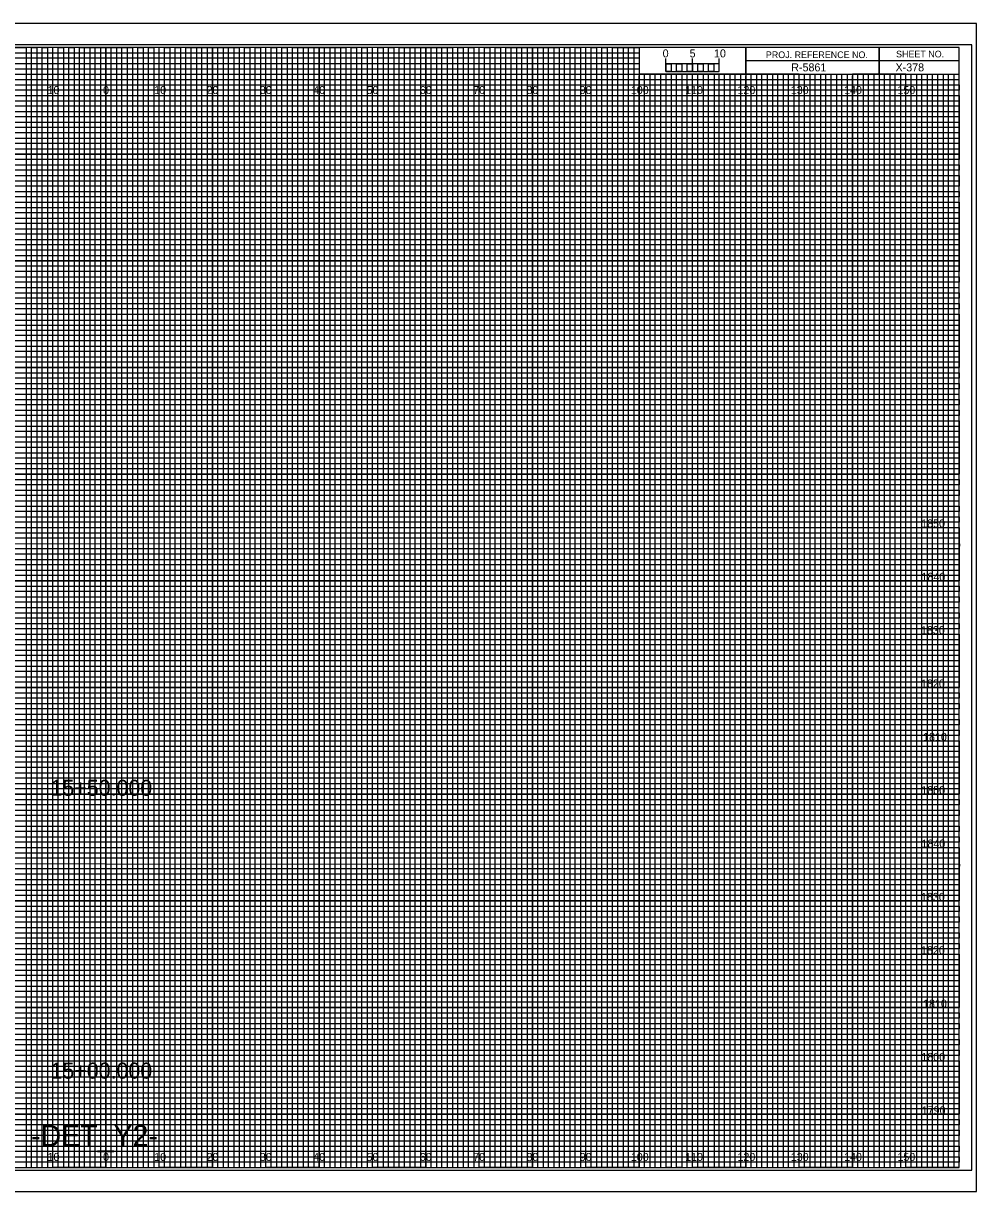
# Model space of a CAD drawing. Extents: x -13 to 323, y -5 to 874.
# Drawn here: x 144.5 to 323.3, y 655.5 to 874.5 of the extents above; entities that cross this region are included whole.
import ezdxf

# ---------------------------------------------------------------- set-up
doc = ezdxf.new("R2010")
doc.units = 0
for name, color, linetype in [('Prop Horizontal Alignment', 7, 'Continuous'), ('Prop XS Alignment Label', 7, 'Continuous'), ('Prop XS Bar Scale Labels', 7, 'Continuous'), ('Prop XS Earthwork Shape', 7, 'Continuous'), ('Prop XS Project Number', 7, 'Continuous'), ('Prop XS Sheet Number', 7, 'Continuous'), ('Raster_Level_0', 7, 'Continuous'), ('Scratch_Level_3', 7, 'Continuous'), ('Sheet Cross Section CELL', 7, 'Continuous'), ('Sheet Cross Section Grid Middle CELL', 7, 'Continuous'), ('Sheet Cross Section Grid Minor 1 CELL', 7, 'Continuous'), ('Sheet Cross Section Grid Minor 2 CELL', 7, 'Continuous'), ('Sheet Cross Section Scale CELL', 7, 'Continuous'), ('Sheet Cutting Line CELL', 7, 'Continuous'), ('Sheet DOT Grid CELL', 7, 'Continuous'), ('Sheet Plot Border Inside CELL', 7, 'Continuous'), ('Sheet Plot Border Outside CELL', 7, 'Continuous')]:
    doc.layers.add(name, color=color, linetype=linetype)

msp = doc.modelspace()

# ---------------------------------------------------------------- linework, layer by layer
at = {"layer": 'Prop XS Earthwork Shape'}
for p, q in [((150, 870), (140, 870)), ((150, 660), (150, 870)), ((170, 870), (160, 870)), ((160, 870), (160, 660)), ((170, 660), (170, 870)), ((190, 870), (180, 870)), ((180, 870), (180, 660)), ((190, 660), (190, 870)), ((210, 870), (200, 870)), ((200, 870), (200, 660)), ((210, 660), (210, 870)), ((230, 870), (220, 870)), ((220, 870), (220, 660)), ((230, 660), (230, 870)), ((250, 870), (240, 870)), ((240, 870), (240, 660)), ((250, 660), (250, 870)), ((260, 870), (260, 660)), ((270, 660), (270, 865)), ((290, 865), (280, 865)), ((280, 865), (280, 660)), ((290, 660), (290, 865)), ((310, 865), (300, 865)), ((300, 865), (300, 660)), ((310, 660), (310, 865)), ((160, 660), (150, 660)), ((180, 660), (170, 660)), ((200, 660), (190, 660)), ((220, 660), (210, 660)), ((240, 660), (230, 660)), ((260, 660), (250, 660)), ((280, 660), (270, 660)), ((300, 660), (290, 660)), ((320, 660), (310, 660)), ((320, 660), (320, 660))]:
    msp.add_line(p, q, dxfattribs=at)
for points in [[(0, 860), (320, 860), (320, 850), (0, 850)], [(0, 840), (320, 840), (320, 830), (0, 830)], [(0, 820), (320, 820), (320, 810), (0, 810)], [(0, 800), (320, 800), (320, 790), (0, 790)], [(0, 780), (320, 780), (320, 770), (0, 770)], [(0, 760), (320, 760), (320, 750), (0, 750)], [(0, 740), (320, 740), (320, 730), (0, 730)], [(0, 720), (320, 720), (320, 710), (0, 710)], [(0, 700), (320, 700), (320, 690), (0, 690)], [(0, 680), (320, 680), (320, 670), (0, 670)]]:
    msp.add_lwpolyline(points, dxfattribs=at)
at = {"layer": 'Sheet Cross Section CELL'}
for p, q in [((305, 870), (305, 865)), ((305, 865), (305, 870)), ((280, 867.5), (280, 865)), ((320, 867.49), (280, 867.49)), ((280, 865), (320, 865))]:
    msp.add_line(p, q, dxfattribs=at)
for points in [[(320, 870), (0, 870), (0, 660), (320, 660)], [(280, 870), (260, 870), (260, 865.03), (280, 865.03)], [(320, 870), (280, 870), (280, 865), (320, 865)]]:
    msp.add_lwpolyline(points, close=True, dxfattribs=at)
at = {"layer": 'Sheet Cross Section Grid Middle CELL'}
for points in [[(135, 870), (145, 870), (145, 660), (155, 660), (155, 870), (165, 870), (165, 660), (175, 660), (175, 870), (185, 870), (185, 660), (195, 660), (195, 870), (205, 870), (205, 660), (215, 660), (215, 870), (225, 870), (225, 660), (235, 660), (235, 870), (245, 870), (245, 660), (255, 660), (255, 870), (259.93, 870), (260, 870), (260, 865), (264.99, 865), (264.99, 660), (275, 660), (275, 865), (285, 865), (285, 660), (295, 660), (295, 865), (305, 865), (305, 660), (315, 660), (315, 865)], [(0, 865), (275, 865)], [(0, 845), (320, 845), (320, 855), (0, 855)], [(0, 825), (320, 825), (320, 835), (0, 835)], [(0, 805), (320, 805), (320, 815), (0, 815)], [(0, 785), (320, 785), (320, 795), (0, 795)], [(0, 765), (320, 765), (320, 775), (0, 775)], [(0, 745), (320, 745), (320, 755), (0, 755)], [(0, 725), (320, 725), (320, 735), (0, 735)], [(0, 705), (320, 705), (320, 715), (0, 715)], [(0, 685), (320, 685), (320, 695), (0, 695)], [(0, 665), (320, 665), (320, 675), (0, 675)]]:
    msp.add_lwpolyline(points, dxfattribs=at)
at = {"layer": 'Sheet Cross Section Grid Minor 1 CELL'}
for p, q in [((0, 869), (260, 869)), ((260, 867.98), (0, 867.98)), ((260, 869), (260, 867.98)), ((0, 867), (260, 867)), ((260, 865.89), (0, 865.89)), ((260, 867), (260, 865.89)), ((0, 864), (320, 864))]:
    msp.add_line(p, q, dxfattribs=at)
for points in [[(0, 863), (270, 863), (320, 863), (320, 862), (0, 862)], [(0, 861), (320, 861), (320, 859), (0, 859)], [(0, 858), (320, 858), (320, 857), (0, 856.98)], [(0, 856), (320, 856), (320, 854), (0, 854)], [(0, 853), (320, 853), (320, 852), (0, 852)], [(0, 851), (320, 851), (320, 849), (0, 849)], [(0, 848), (320, 848), (320, 847), (0, 847)], [(0, 846), (320, 846), (320, 844), (0, 844)], [(0, 843), (320, 843), (320, 842), (0, 842)], [(0, 841), (320, 841), (320, 839), (0, 839)], [(0, 838), (320, 838), (320, 837), (0, 837)], [(0, 836), (320, 836), (320, 833.95), (320, 833), (320, 832), (0, 832)], [(0, 834), (320, 834), (320, 833), (0, 833)], [(0, 831), (320, 831), (320, 829), (0, 829.03)], [(0, 829.03), (320, 829), (320, 828), (0, 828)], [(0, 827), (320, 827), (320, 826), (0, 826)], [(0, 824), (320, 824), (320, 823), (0, 823)], [(0, 822), (320, 822), (320, 821), (0, 821)], [(-0.07, 818.89), (320, 818.89), (320, 817.88), (-0.07, 817.88)], [(0, 817), (320, 817), (320, 816), (0, 816)], [(0, 814), (320, 814), (320, 813), (0, 813)], [(0, 812), (320, 812), (320, 811), (0, 811)], [(0, 809), (320, 809), (320, 808), (0, 808)], [(0, 807), (320, 807), (320, 806), (0, 806)], [(0, 804), (320, 804), (320, 803), (0, 803)], [(0, 802), (320, 802), (320, 801), (0, 801)], [(0, 799), (320, 799), (319.99, 797.98), (0, 798)], [(0, 797), (320, 797), (320, 796), (0, 796)], [(0, 794), (320, 794), (320, 793), (0, 793)], [(0, 792), (320, 792), (320, 791), (0, 791)], [(0, 789), (320, 789), (320, 788), (0, 788)], [(0, 787), (320, 787), (320, 786), (0, 786)], [(0, 784), (320, 784), (320, 783), (0, 783)], [(0, 782), (320, 782), (320, 781), (0, 781)], [(0, 779), (320, 779), (320, 778), (0, 778)], [(0, 776.99), (320.07, 776.91), (320, 776), (0, 776)], [(0, 774), (320, 774), (320, 773), (0, 773)], [(0, 772), (320, 772), (320, 771), (0, 771)], [(0, 769), (320, 769), (320, 768), (0, 768)], [(0, 767), (320, 767), (320, 766), (0, 766)], [(0, 764), (320, 764), (320, 763), (0, 763)], [(0, 762), (320, 762), (320, 761), (0, 761)], [(0, 759), (320, 759), (320, 758), (0, 758)], [(0, 757), (320, 757), (320, 756), (0, 756)], [(0, 754), (320, 754), (320, 753), (0, 753)], [(0, 752), (320, 752), (320, 751), (0, 751)], [(0, 749), (320, 749), (320, 748), (0, 748)], [(0, 747), (320, 747), (320, 746), (0, 746)], [(0, 744), (320, 744), (320, 743), (0, 743)], [(0, 742), (320, 742), (320, 741), (0, 741)], [(0, 739), (320, 739), (319.99, 737.98), (0, 738)], [(0, 737), (320, 737), (320, 736), (0, 736)], [(0, 734), (320, 734), (320, 733), (0, 733)], [(0, 732), (320, 732), (320, 731), (0, 731)], [(0, 729), (320, 729), (320, 728), (0, 728)], [(0, 727), (320, 727), (320, 726), (0, 726)], [(0, 724), (320, 724), (320, 723), (0, 723)], [(0, 722), (320, 722), (320, 721), (0, 721)], [(0, 719), (320, 719), (320, 718), (0, 718)], [(0, 716.99), (320.07, 716.91), (320, 716), (0, 716)], [(0, 714), (320, 714), (320, 713), (0, 713)], [(0, 712), (320, 712), (320, 711), (0, 711)], [(0, 709), (320, 709), (320, 708), (0, 708)], [(0, 707), (320, 707), (320, 706), (0, 706)], [(0, 704), (320, 704), (320, 703), (0, 703)], [(0, 702), (320, 702), (320, 701), (0, 701)], [(0, 699), (320, 699), (320, 698), (0, 698)], [(0, 697), (320, 697), (320, 696), (0, 696)], [(0, 694), (320, 694), (320, 693), (0, 693)], [(0, 692), (320, 692), (320, 691), (0, 691)], [(0, 689), (320, 689), (320, 688), (0, 688)], [(0, 687), (320, 687), (320, 686), (0, 686)], [(0, 684), (320, 684), (320, 683), (0, 683)], [(0, 682), (320, 682), (320, 681), (0, 681)], [(0, 679), (320, 679), (320, 678), (0, 678)], [(0, 677), (320, 677), (320, 676), (0, 676)], [(0, 674), (320, 674), (320, 673), (0, 673)], [(0, 672), (320, 672), (320, 671), (0, 671)], [(0, 669), (320, 669), (320, 668), (0, 668)], [(0, 667), (320, 667), (320, 666), (0, 666)], [(0, 664), (320, 664), (320, 663), (0, 663)], [(0, 662), (320, 662), (320, 661), (0, 661)]]:
    msp.add_lwpolyline(points, dxfattribs=at)
at = {"layer": 'Sheet Cross Section Grid Minor 2 CELL'}
for p, q in [((267, 865), (266.01, 865)), ((266.01, 865), (266.01, 660)), ((267, 660), (267, 865)), ((269, 865), (268, 865)), ((268, 865), (268, 660)), ((269, 660), (269, 865)), ((266.01, 660), (265, 660)), ((268, 660), (267, 660))]:
    msp.add_line(p, q, dxfattribs=at)
for points in [[(145, 660), (146, 660), (146, 870), (147, 870), (147, 660)], [(147, 660), (148, 660), (148, 870), (149, 870), (149, 660)], [(150, 660), (151, 660), (151, 870), (152, 870), (152, 660)], [(152, 660), (153, 660), (153, 870), (154, 870), (154, 660)], [(155, 660), (156, 660), (156, 870), (157, 870), (157, 660)], [(157, 660), (158, 660), (158, 870), (159, 870), (159, 660)], [(160, 660), (161, 660), (161, 870), (162, 870), (162, 660)], [(162, 660), (163, 660), (163, 870), (164, 870), (164, 660)], [(165, 660), (166, 660), (166, 870), (167, 870), (167, 660)], [(167, 660), (168, 660), (168, 870), (169, 870), (169, 660)], [(170, 660), (171, 660), (171, 870), (172, 870), (172, 660)], [(172, 660), (173, 660), (173, 870), (174, 870), (174, 660)], [(175, 660), (176, 660), (176, 870), (177, 870), (177, 660)], [(177, 660), (178, 660), (178, 870), (179, 870), (179, 660)], [(180, 660), (181, 660), (181, 870), (182, 870), (182, 660)], [(182, 660), (183, 660), (183, 870), (184, 870), (184, 660)], [(185, 660), (186, 660), (186, 870), (187, 870), (187, 660)], [(187, 660), (188, 660), (188, 870), (189, 870), (189, 660)], [(190, 660), (191, 660), (191, 870), (192, 870), (192, 660)], [(192, 660), (193, 660), (193, 870), (194, 870), (194, 660)], [(195, 660), (196, 660), (196, 870), (197, 870), (197, 660)], [(197, 660), (198, 660), (198, 870), (199, 870), (199, 660)], [(200, 660), (201, 660), (201, 870), (202, 870), (202, 660)], [(202, 660), (203, 660), (203, 870), (204, 870), (204, 660)], [(205, 660), (206, 660), (206, 870), (207, 870), (207, 660)], [(207, 660), (208, 660), (208, 870), (209, 870), (209, 660)], [(210, 660), (211, 660), (211, 870), (212, 870), (212, 660)], [(212, 660), (213, 660), (213, 870), (214, 870), (214, 660)], [(215, 660), (216, 660), (216, 870), (217, 870), (217, 660)], [(217, 660), (218, 660), (218, 870), (219, 870), (219, 660)], [(220, 660), (221, 660), (221, 870), (222, 870), (222, 660)], [(222, 660), (223, 660), (223, 870), (224, 870), (224, 660)], [(225, 660), (226, 660), (226, 870), (227, 870), (227, 660)], [(227, 660), (228, 660), (228, 870), (229, 870), (229, 660)], [(230, 660), (231, 660), (231, 870), (232, 870), (232, 660)], [(232, 660), (233, 660), (233, 870), (234, 870), (234, 660)], [(235, 660), (236, 660), (236, 870), (237, 870), (237, 660)], [(237, 660), (238, 660), (238, 870), (239, 870), (239, 660)], [(240, 660), (241, 660), (241, 870), (242, 870), (242, 660)], [(242, 660), (243, 660), (243, 870), (244, 870), (244, 660)], [(245, 660), (246, 660), (246, 870), (247, 870), (247, 660)], [(247, 660), (248, 660), (248, 870), (249, 870), (249, 660)], [(250, 660), (251, 660), (251, 870), (252, 870), (252, 660)], [(252, 660), (253, 660), (253, 870), (254, 870), (254, 660)], [(255, 660), (256, 660), (256, 870), (257, 870), (257, 660)], [(257, 660), (258, 660), (258, 870), (259, 870), (259, 660)], [(260, 660), (261, 660), (261, 865), (262.02, 865), (262.02, 660)], [(262, 660), (263, 660), (263, 865), (263.99, 865), (263.99, 660)], [(270, 660), (270.98, 660), (270.98, 865), (272, 865), (272, 660)], [(272, 660), (273, 660), (273, 865), (274.05, 865), (274.05, 660)], [(275, 660), (276, 660), (276, 865), (277, 865), (277, 660)], [(277, 660), (278, 660), (278, 865), (279, 865), (279, 660)], [(280, 660), (281, 660), (281, 865), (282, 865), (282, 660)], [(282, 660), (283, 660), (283, 865), (284, 865), (284, 660)], [(285, 660), (286, 660), (286, 865), (287, 865), (287, 660)], [(287, 660), (288, 660), (288, 865), (289, 865), (289, 660)], [(290, 660), (291, 660), (291, 865), (292, 865), (292, 660)], [(292, 660), (293, 660), (293, 865), (294, 865), (294, 660)], [(295, 660), (296, 660), (296, 865), (297, 865), (297, 660)], [(297, 660), (298, 660), (298, 865), (299, 865), (299, 660)], [(300, 660), (301, 660), (301, 865), (302, 865), (302, 660)], [(302, 660), (303, 660), (303, 865), (304, 865), (304, 660)], [(305, 660), (306, 660), (306, 865), (307, 865), (307, 660)], [(307, 660), (308, 660), (308, 865), (309, 865), (309, 660)], [(310, 660), (311, 660), (311, 865), (312, 865), (312, 660)], [(312, 660), (313, 660), (313, 865), (314, 865), (314, 660)], [(315, 660), (316, 660), (316, 865), (317, 865), (317, 660)], [(317, 660), (318, 660), (318, 865), (319, 865), (319, 660)]]:
    msp.add_lwpolyline(points, dxfattribs=at)
at = {"layer": 'Sheet Cross Section Scale CELL'}
for p, q in [((265, 865.49), (265, 867.9)), ((265, 866.9), (265, 867.9)), ((270, 865.49), (270, 867.9)), ((275, 865.49), (275, 867.9)), ((275, 866.9), (275, 867.9))]:
    msp.add_line(p, q, dxfattribs=at)
for points in [[(275, 866.9), (265, 866.9), (265, 865.49), (275, 865.49)], [(265, 866.9), (266, 866.9), (266, 865.49), (265, 865.49)], [(267, 866.9), (268, 866.9), (268, 865.49), (267, 865.49)], [(269, 866.9), (270, 866.9), (270, 865.49), (269, 865.49)], [(271, 866.9), (272, 866.9), (272, 865.49), (271, 865.49)], [(273, 866.9), (274, 866.9), (274, 865.49), (273, 865.49)]]:
    msp.add_lwpolyline(points, close=True, dxfattribs=at)
at = {"layer": 'Sheet Cutting Line CELL'}
for p, q in [((323.3, 874.5), (-13.4, 874.5)), ((-13.4, 655.5), (323.3, 655.5))]:
    msp.add_line(p, q, dxfattribs=at)
at = {"layer": 'Sheet DOT Grid CELL'}
for p, q in [((150, 660), (150, 870)), ((160, 660), (160, 870)), ((170, 660), (170, 870)), ((180, 660), (180, 870)), ((190, 660), (190, 870)), ((200, 660), (200, 870)), ((210, 660), (210, 870)), ((220, 660), (220, 870)), ((230, 660), (230, 870)), ((240, 660), (240, 870)), ((250, 660), (250, 870)), ((260, 660), (260, 864.69)), ((270, 660), (270, 864.69)), ((280, 660), (280, 864.69)), ((290, 660), (290, 864.69)), ((300, 660), (300, 864.69)), ((310, 660), (310, 864.69)), ((0, 860), (320, 860)), ((0, 850), (320, 850)), ((0, 840), (320, 840)), ((0, 830), (320, 830)), ((0, 820), (320, 820)), ((0, 810), (320, 810)), ((0, 800), (320, 800)), ((0, 790), (320, 790)), ((0, 780), (320, 780)), ((0, 770), (320, 770)), ((0, 760), (320, 760)), ((0, 750), (320, 750)), ((0, 740), (320, 740)), ((0, 730), (320, 730)), ((0, 720), (320, 720)), ((0, 710), (320, 710)), ((0, 700), (320, 700)), ((0, 690), (320, 690)), ((0, 680), (320, 680)), ((0, 670), (320, 670))]:
    msp.add_line(p, q, dxfattribs=at)
at = {"layer": 'Sheet Plot Border Inside CELL'}
msp.add_lwpolyline([(-10.8, 659.5), (322.4, 659.5), (322.4, 870.5), (-10.8, 870.5)], close=True, dxfattribs=at)
at = {"layer": 'Sheet Plot Border Outside CELL'}
msp.add_lwpolyline([(-13.4, 655.5), (323.3, 655.5), (323.3, 874.5), (-13.4, 874.5)], close=True, dxfattribs=at)

# ---------------------------------------------------------------- texts
at = {"layer": 'Prop Horizontal Alignment'}
for s, p in [('15+50.000', (149.59, 729.7)), ('15+00.000', (149.59, 676.68))]:
    msp.add_text(s, height=3, dxfattribs=at).set_placement(p)
at = {"layer": 'Prop XS Alignment Label'}
msp.add_text('-DET_Y2-', height=4, dxfattribs=at).set_placement((145.96, 664))
at = {"layer": 'Prop XS Bar Scale Labels'}
for s, p in [('5', (269.47, 868.12)), ('10', (274.04, 868.12))]:
    msp.add_text(s, height=1.5, dxfattribs=at).set_placement(p)
at = {"layer": 'Prop XS Project Number'}
msp.add_text('R-5861', height=1.5, dxfattribs=at).set_placement((288.53, 865.5))
at = {"layer": 'Prop XS Sheet Number'}
msp.add_text('X-378', height=1.5, dxfattribs=at).set_placement((308.09, 865.5))
at = {"layer": 'Raster_Level_0'}
for s, p in [('10', (149.04, 861.25)), ('0', (159.45, 861.25)), ('0', (159.45, 861.25)), ('10', (169.04, 861.25)), ('20', (178.86, 861.25)), ('30', (188.86, 861.25)), ('40', (198.86, 861.25)), ('50', (208.86, 861.25)), ('60', (218.86, 861.25)), ('70', (228.86, 861.25)), ('80', (238.86, 861.25)), ('90', (248.86, 861.25)), ('100', (258.44, 861.25)), ('110', (268.62, 861.25)), ('120', (278.44, 861.25)), ('130', (288.44, 861.25)), ('140', (298.44, 861.25)), ('150', (308.44, 861.25)), ('10', (149.04, 661.25)), ('0', (159.45, 661.25)), ('0', (159.45, 661.25)), ('10', (169.04, 661.25)), ('20', (178.86, 661.25)), ('30', (188.86, 661.25)), ('40', (198.86, 661.25)), ('50', (208.86, 661.25)), ('60', (218.86, 661.25)), ('70', (228.86, 661.25)), ('80', (238.86, 661.25)), ('90', (248.86, 661.25)), ('100', (258.44, 661.25)), ('110', (268.62, 661.25)), ('120', (278.44, 661.25)), ('130', (288.44, 661.25)), ('140', (298.44, 661.25)), ('150', (308.44, 661.25))]:
    msp.add_text(s, height=1.5, dxfattribs=at).set_placement(p)
at = {"layer": 'Scratch_Level_3'}
for s, p in [('1850', (312.9, 780)), ('1840', (312.95, 770)), ('1830', (312.86, 760)), ('1820', (312.87, 750)), ('1810', (313.25, 740)), ('1850', (312.9, 730)), ('1800', (312.92, 730)), ('1840', (312.95, 720)), ('1830', (312.86, 710)), ('1820', (312.87, 700)), ('1810', (313.25, 690)), ('1800', (312.92, 680)), ('1790', (313, 670))]:
    msp.add_text(s, height=1.5, dxfattribs=at).set_placement(p)
at = {"layer": 'Sheet Cross Section CELL'}
for s, p in [('PROJ. REFERENCE NO.', (283.77, 867.99)), ('SHEET NO.', (308.19, 868.12))]:
    msp.add_text(s, height=1.25, dxfattribs=at).set_placement(p)
at = {"layer": 'Sheet Cross Section Scale CELL'}
msp.add_text('0', height=1.5, dxfattribs=at).set_placement((264.41, 868.12))

doc.saveas('drawing.dxf')
